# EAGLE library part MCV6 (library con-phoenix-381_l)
Mini-Combicon 3.81mm vertikal 6polig (ohne Gegenstecker)
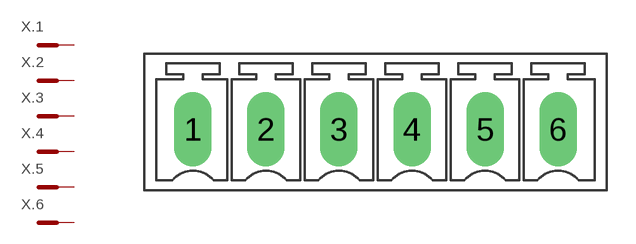
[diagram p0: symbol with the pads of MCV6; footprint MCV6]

Designator prefix X; gates .1=MCST .2=MCST .3=MCST .4=MCST .5=MCST .6=MCST

## MCV6  [MCV6]
1  .1:SK  pas
2  .2:SK  pas
3  .3:SK  pas
4  .4:SK  pas
5  .5:SK  pas
6  .6:SK  pas

## Footprint MCV6 (pad centres in mm)
Mini-Combicon 3.81mm vertikal 6-polig (ohne Gegenstecker)
drill 1.3 pad 1.905 long: 1 -9.525,0; 2 -5.715,0; 3 -1.905,0; 4 1.905,0; 5 5.715,0; 6 9.525,0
